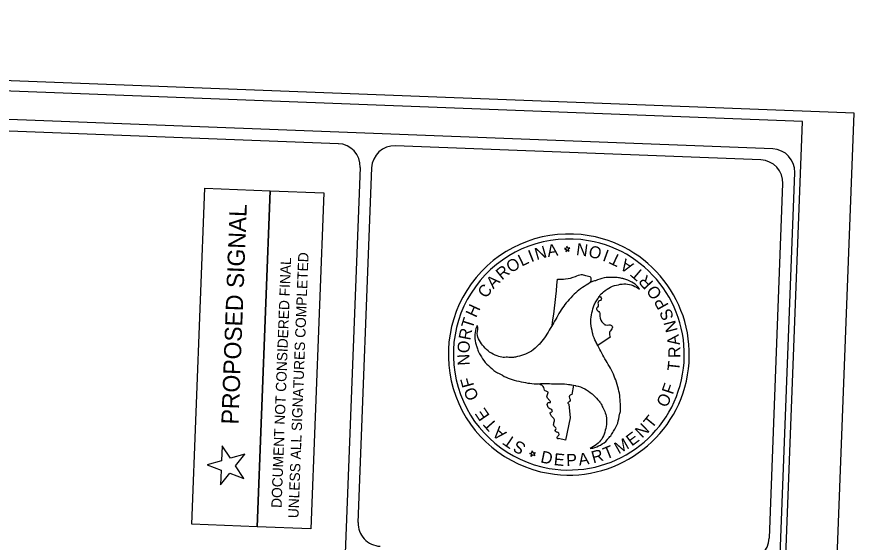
# Model space of a CAD drawing. Extents: x 2094564 to 2100382, y 679033 to 692366.
# Drawn here: x 2098550 to 2100382, y 689554 to 690703 of the extents above; entities that cross this region are included whole.
import ezdxf

# ---------------------------------------------------------------- set-up
doc = ezdxf.new("R2010")
doc.units = 0
for name, color, linetype in [('Pattern 17', 7, 'Continuous'), ('Prop DSN Text', 7, 'Continuous'), ('Prop Horizontal Alignment', 7, 'Continuous'), ('Prop Horizontal Alignment Direction Label', 7, 'Continuous'), ('Prop Horizontal Alignment Tick Label', 7, 'Continuous'), ('Prop Horizontal Alignment Tick Large', 7, 'Continuous'), ('Prop RDY Traffic Signal CELL', 7, 'Continuous')]:
    doc.layers.add(name, color=color, linetype=linetype)

msp = doc.modelspace()

# ---------------------------------------------------------------- linework, layer by layer
at = {"layer": 'Pattern 17'}
msp.add_lwpolyline([(2098933.6, 689593.4), (2098961.8, 690327.9), (2099104.6, 690322.4), (2099076.4, 689588)], close=True, dxfattribs=at)
at = {"layer": 'Prop Horizontal Alignment'}
for p, q in [((2099076.4, 689588), (2099104.6, 690322.4)), ((2099104.6, 690322.4), (2099222, 690317.9)), ((2099222, 690317.9), (2099193.8, 689583.5)), ((2099193.8, 689583.5), (2099076.4, 689588))]:
    msp.add_line(p, q, dxfattribs=at)
at = {"layer": 'Prop Horizontal Alignment Direction Label'}
for p, q in [((2099030, 683278.9), (2099302.1, 690373.6)), ((2099297.3, 689597.1), (2099327.1, 690372.7)), ((2099802.8, 690224.3), (2099802.8, 690224.3)), ((2099752.9, 690197), (2099748.5, 690196.2)), ((2099748.5, 690196.2), (2099752.4, 690194.1)), ((2099752.4, 690194.1), (2099751.6, 690189.6)), ((2099751.6, 690189.6), (2099754.9, 690192.9)), ((2099753.5, 690201.4), (2099752.9, 690197)), ((2099755.6, 690197.3), (2099753.5, 690201.4)), ((2099754.9, 690192.9), (2099759, 690190.8)), ((2099760.2, 690197.9), (2099755.6, 690197.3)), ((2099756.9, 690194.7), (2099760.2, 690197.9)), ((2099759, 690190.8), (2099756.9, 690194.7)), ((2099557, 690027.5), (2099557.5, 690027)), ((2099557, 690027.5), (2099557.5, 690027)), ((2099721.4, 690027.8), (2099721.4, 690027.8)), ((2099848.7, 690002.1), (2099821.3, 689984.4)), ((2099821.3, 689984.4), (2099821.3, 689984.4)), ((2099768.6, 689897.6), (2099764.8, 689877.1)), ((2099757.9, 689855.9), (2099761.3, 689826.2)), ((2099761.3, 689826.2), (2099751, 689777.3)), ((2099751, 689777.3), (2099735.4, 689780.5)), ((2099672.8, 689748.3), (2099677.2, 689749.2)), ((2099676.8, 689746.4), (2099672.8, 689748.3)), ((2099676, 689741.8), (2099676.8, 689746.4)), ((2099677.2, 689749.2), (2099678, 689753.6)), ((2099678, 689753.6), (2099680.1, 689749.5)), ((2099680.1, 689749.5), (2099684.6, 689750.1)), ((2099684.6, 689750.1), (2099681.3, 689746.9)), ((2099681.3, 689746.9), (2099683.4, 689742.9)), ((2099679.3, 689745), (2099676, 689741.8)), ((2099683.4, 689742.9), (2099679.3, 689745))]:
    msp.add_line(p, q, dxfattribs=at)
for points in [[(2100204.3, 690414.1), (2095058.2, 690611.5)], [(2099254.1, 690425.5), (2095082.1, 690585.5)], [(2100178.4, 690390.1), (2099379, 690420.7)], [(2099968.8, 682967.7), (2100252.4, 690362.2)], [(2100196.7, 689562.6), (2100226.4, 690338.2)]]:
    msp.add_lwpolyline(points, dxfattribs=at)
for centre, radius, start, end in [((2099251.9, 690375.6), 50, 357.8037, 87.8037), ((2099376.8, 690370.8), 50, 87.8037, 177.8037), ((2100202.2, 690364.2), 50, 357.8037, 87.8037), ((2100176.2, 690340.1), 50, 357.8037, 87.8037), ((2099758.1, 689964.5), 263.6, 80.2248, 260.2248), ((2099758.1, 689964.5), 263.6, 260.2248, 80.2248), ((2099758.1, 689964.5), 252.6, 80.2248, 260.2248), ((2099758.1, 689964.5), 252.6, 260.2248, 80.2248), ((2098347.5, 690237), 1389.7, 351.3424, 355.5484), ((2098347.5, 690237), 1389.7, 345.9033, 346.0029), ((2099347.3, 689595.2), 50, 177.8037, 267.8037), ((2100146.4, 689564.6), 50, 267.8037, 357.8037)]:
    msp.add_arc(centre, radius, start, end, dxfattribs=at)
for points in [[(2099912.9, 690107.3), (2099909.5, 690112), (2099895.6, 690122.8), (2099878.2, 690129.9), (2099876.5, 690130.4), (2099866.6, 690132.3), (2099854.7, 690132.9), (2099835.1, 690131.9), (2099816.2, 690125.9), (2099808.2, 690123.4), (2099800, 690118.6), (2099783.7, 690108.1), (2099769.9, 690096.3), (2099755.6, 690080.8), (2099744.2, 690066.4), (2099734.2, 690049.9), (2099724.7, 690033.3), (2099715.1, 690017.6), (2099704.8, 690001), (2099692.9, 689986.7), (2099691.6, 689985.5), (2099676.2, 689972), (2099658.6, 689963.8), (2099641.2, 689959), (2099632.3, 689958), (2099621, 689958.4), (2099614.5, 689958.3), (2099601.6, 689961.5), (2099584.8, 689969.8), (2099572.1, 689981.7), (2099562.7, 689994.8), (2099557.8, 690010.5), (2099557.5, 690027), (2099557, 690027.5)], [(2099733, 690129.1), (2099751, 690129.8), (2099772.9, 690135.4), (2099785.1, 690139.3), (2099794.7, 690137.5), (2099805.8, 690133.3), (2099805, 690122)], [(2099805.1, 690121.9), (2099800, 690118.6), (2099783.7, 690108.1), (2099769.9, 690096.3), (2099755.6, 690080.8), (2099744.2, 690066.4), (2099734.2, 690049.9), (2099724.7, 690033.3), (2099721.4, 690027.8)], [(2099804.7, 689759.1), (2099810.9, 689760), (2099827.1, 689766.6), (2099841.9, 689778), (2099842.9, 689779.4), (2099849.8, 689787), (2099856.1, 689796.8), (2099865, 689814.5), (2099869.3, 689833.7), (2099871.1, 689841.9), (2099871, 689851.6), (2099870, 689870.7), (2099866.8, 689888.5), (2099860.6, 689908.8), (2099853.9, 689925.8), (2099844.5, 689942.6), (2099834.8, 689959.2), (2099826, 689975.6), (2099817.1, 689992.6), (2099810.4, 690010.2), (2099810, 690012.1), (2099806.1, 690032.1), (2099807.7, 690051.2), (2099812.2, 690068.4), (2099815.7, 690077.3), (2099821.8, 690086.5), (2099825, 690092.3), (2099834.2, 690101.9), (2099849.6, 690112), (2099866.4, 690117.2), (2099882.6, 690118.9), (2099898.6, 690115.3), (2099912.9, 690107.3)], [(2099821.3, 689984.4), (2099817.1, 689992.6), (2099810.4, 690010.2), (2099810, 690012.1), (2099806.1, 690032.1), (2099807.7, 690051.2), (2099812.2, 690068.4), (2099815.7, 690077.3), (2099821.8, 690086.5), (2099824.8, 690091.9)], [(2099824.9, 690091.8), (2099829, 690088.6), (2099828.7, 690084.6), (2099822, 690078.7), (2099822.3, 690070), (2099819.4, 690066.6), (2099818.8, 690064.1), (2099825.4, 690056.7), (2099825.8, 690048), (2099833.4, 690032.8), (2099838.7, 690029.1), (2099851.4, 690027.9), (2099853.3, 690024.2), (2099852, 690020.3), (2099847.3, 690012.5), (2099848.7, 690002.1)], [(2099557.5, 690027), (2099555, 690021.4), (2099552.7, 690004), (2099555.3, 689985.5), (2099555.9, 689983.8), (2099559, 689974.2), (2099564.3, 689963.7), (2099575.2, 689947.3), (2099589.7, 689933.7), (2099596, 689928.2), (2099604.1, 689923.6), (2099621.4, 689914.6), (2099638.6, 689908.6), (2099659.1, 689903.9), (2099677.3, 689901), (2099696.4, 689900.8), (2099715.7, 689900.8), (2099734.3, 689900.4), (2099753.4, 689899.7), (2099772, 689896.6), (2099773.6, 689896.3), (2099792.8, 689889.5), (2099808.8, 689878.5), (2099821.5, 689865.7), (2099827.2, 689858.5), (2099832.5, 689848.6), (2099835.5, 689843), (2099839.5, 689830.2), (2099840.6, 689811.7), (2099836.6, 689794.5), (2099830, 689779.7), (2099819, 689767.7), (2099804.7, 689759.1)], [(2099735.4, 689780.5), (2099733.9, 689780.2), (2099732.6, 689783.1), (2099736.9, 689789.9), (2099734.4, 689794.2), (2099731.2, 689794.6), (2099728.5, 689798), (2099730.4, 689802.9), (2099725.4, 689808.4), (2099725.1, 689812.7), (2099726.6, 689821.5), (2099718, 689833.7), (2099718.1, 689838.2), (2099721.1, 689838.8), (2099722.1, 689841.4), (2099714.2, 689847.3), (2099713.2, 689848.7), (2099711.3, 689857.4), (2099713.3, 689859.3), (2099717.2, 689859.3), (2099718.2, 689860.3), (2099716.7, 689863.3), (2099712.7, 689867.7), (2099710.4, 689875), (2099712.7, 689882.5), (2099706.6, 689884.9), (2099702.2, 689894.8), (2099698.9, 689897.3), (2099695.3, 689898.4)], [(2099695.9, 689900.8), (2099696.4, 689900.8), (2099715.7, 689900.8), (2099734.3, 689900.4), (2099753.4, 689899.7), (2099768.6, 689897.5)], [(2099764.8, 689877.1), (2099760.7, 689875.7), (2099758.9, 689871.9), (2099760.8, 689866), (2099759.9, 689862), (2099755.9, 689858.1), (2099757.9, 689855.9)]]:
    msp.add_spline(points, degree=3, dxfattribs=at)
at = {"layer": 'Prop Horizontal Alignment Tick Label'}
msp.add_lwpolyline([(2099950.1, 682147.8), (2100269.5, 690474.2), (2094997.8, 690676.3), (2094678.5, 682349.9)], close=True, dxfattribs=at)
at = {"layer": 'Prop Horizontal Alignment Tick Large'}
msp.add_lwpolyline([(2094886.5, 690703.1), (2094563.9, 682289.3), (2100059.8, 682078.5), (2100382.4, 690492.3)], close=True, dxfattribs=at)
at = {"layer": 'Prop RDY Traffic Signal CELL'}
msp.add_lwpolyline([(2098997.8, 689711.9), (2098996.5, 689679.3), (2099016.7, 689705), (2099047.4, 689693.7), (2099029.2, 689720.9), (2099049.4, 689746.5), (2099018, 689737.6), (2098999.8, 689764.8), (2098998.5, 689732.1), (2098967.1, 689723.2), (2098997.8, 689711.9)], dxfattribs=at)

# ---------------------------------------------------------------- texts
at = {"layer": 'Prop DSN Text'}
msp.add_text('PROPOSED SIGNAL', height=37.5, rotation=87.8037, dxfattribs=at).set_placement((2099035.4, 689811))
at = {"layer": 'Prop Horizontal Alignment'}
for s, p in [('UNLESS ALL SIGNATURES COMPLETED', (2099166.6, 689606.2)), ('DOCUMENT NOT CONSIDERED FINAL', (2099129.7, 689628.7))]:
    msp.add_text(s, height=22.5, rotation=87.8037, dxfattribs=at).set_placement(p)
at = {"layer": 'Prop Horizontal Alignment Direction Label'}
for s, height, rotation, p in [('A', 26.3, 8.6882, (2099712.5, 690177.7)), ('N', 26.3, 172.433, (2099801.7, 690205)), ('I', 26.3, 21.8203, (2099675.7, 690166.1)), ('N', 26.3, 16.1202, (2099687.7, 690170.7)), ('O', 26.2, 165.1849, (2099832.4, 690197.2)), ('I', 26.3, 160.0493, (2099848.4, 690191.6)), ('O', 26.3, 32.0433, (2099631.4, 690141.8)), ('L', 26.2, 25.8096, (2099655.1, 690156.6)), ('T', 26.2, 154.3994, (2099875.2, 690178.9)), ('A', 26.3, 147.315, (2099901.6, 690162.4)), ('R', 26.3, 39.1629, (2099611.8, 690126)), ('T', 26.2, 139.2279, (2099924.5, 690143.3)), ('A', 26.3, 45.5268, (2099593, 690106.7)), ('R', 26.3, 133.1282, (2099944.6, 690122.3)), ('C', 26.2, 53.0239, (2099577.1, 690085.8)), ('O', 26.3, 125.9391, (2099963.4, 690096.7)), ('P', 26.3, 119.2471, (2099977.4, 690072.3)), ('H', 26.2, 65.3662, (2099555.1, 690043.6)), ('S', 26.2, 112.0552, (2099988.5, 690045.4)), ('T', 26.3, 72.4509, (2099547.1, 690019.1)), ('N', 26.2, 104.8447, (2099996.6, 690016.8)), ('R', 26.3, 79.1006, (2099542.4, 689994.4)), ('A', 26.2, 97.8131, (2100001.3, 689986.1)), ('O', 26.3, 85.7105, (2099540.3, 689966.7)), ('R', 26.3, 91.06, (2100002.3, 689957.1)), ('N', 26.3, 93.2086, (2099541.6, 689941.1)), ('T', 26.2, 84.1034, (2099999.5, 689927.4)), ('F', 26.3, 105.2955, (2099551.3, 689896.4)), ('F', 26.3, 71.1941, (2099985.5, 689875.5)), ('O', 26.3, 112.4424, (2099561.7, 689870.6)), ('O', 26.3, 64.0289, (2099972, 689846.8)), ('E', 26.2, 124.3818, (2099586.1, 689830.9)), ('T', 26.2, 131.4974, (2099603.1, 689811.6)), ('T', 26.2, 50.7252, (2099939.5, 689801.1)), ('A', 26.4, 138.5526, (2099623.4, 689793.5)), ('N', 26.3, 43.8832, (2099918.3, 689780.3)), ('T', 26.3, 145.6049, (2099644.4, 689778.7)), ('E', 26.2, 36.9117, (2099895.8, 689763)), ('S', 26.3, 151.9811, (2099666.5, 689766.9)), ('T', 26.3, 22.2099, (2099839.5, 689734.4)), ('M', 26.2, 29.4449, (2099867, 689746.1)), ('D', 26.3, 348.0778, (2099694.8, 689728.8)), ('E', 26.2, 354.3657, (2099724.4, 689722.8)), ('P', 26.3, 1.8981, (2099752.8, 689720.5)), ('A', 26.2, 8.4907, (2099780.9, 689721.5)), ('R', 26.3, 15.5593, (2099811.6, 689726.4))]:
    msp.add_text(s, height=height, rotation=rotation, dxfattribs=at).set_placement(p)

doc.saveas('drawing.dxf')
